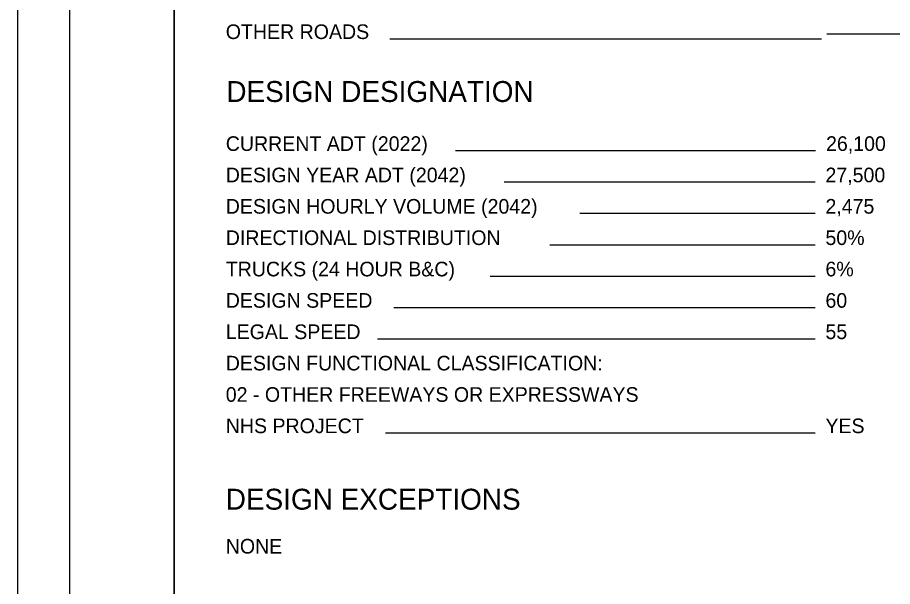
# Model space of a CAD drawing. Extents: x 0 to 34, y 0 to 22.
# Drawn here: x 0 to 8.38, y 5.64 to 11.08 of the extents above; entities that cross this region are included whole.
import ezdxf

# ---------------------------------------------------------------- set-up
doc = ezdxf.new("R2010")
doc.units = 0
for name, color, linetype in [('SH_Border', 7, 'Continuous'), ('SH_Cut_Line', 7, 'Continuous'), ('SH_Data', 7, 'Continuous'), ('SH_Text', 7, 'Continuous')]:
    doc.layers.add(name, color=color, linetype=linetype)

msp = doc.modelspace()

# ---------------------------------------------------------------- linework, layer by layer
at = {"layer": 'SH_Cut_Line'}
for p, q in [((9, 10.9223), (7.75, 10.9223)), ((7.7, 10.8767), (3.5657, 10.8767)), ((7.6424, 9.8062), (4.1936, 9.8062)), ((7.6368, 9.5062), (4.6592, 9.5062)), ((7.6368, 9.2062), (5.3852, 9.2062)), ((7.6368, 8.9062), (5.0988, 8.9062)), ((7.6368, 8.6062), (4.5259, 8.6062)), ((7.6368, 8.3062), (3.6035, 8.3062)), ((7.6368, 8.0062), (3.4488, 8.0062)), ((7.6368, 7.1062), (3.5243, 7.1062))]:
    msp.add_line(p, q, dxfattribs=at)
at = {"layer": 'SH_Data'}
for points in [[(0.5, 21.5), (1.5, 21.5), (1.5, 0.5), (0.5, 0.5)], [(1.5, 21.5), (33.5, 21.5), (33.5, 0.5), (1.5, 0.5)]]:
    msp.add_lwpolyline(points, close=True, dxfattribs=at)
at = {"layer": 'SH_Text'}
msp.add_lwpolyline([(0, 0), (34, 0), (34, 22), (0, 22)], close=True, dxfattribs=at)

# ---------------------------------------------------------------- texts
at = {"layer": 'SH_Border'}
for s, height, p in [('OTHER ROADS', 0.14, (1.9944, 10.8767)), ('CURRENT ADT (2022)', 0.14, (1.9944, 9.8062)), ('26,100', 0.14, (7.7424, 9.8062)), ('DESIGN YEAR ADT (2042)', 0.14, (1.9944, 9.5062)), ('27,500', 0.14, (7.7368, 9.5062)), ('DESIGN HOURLY VOLUME (2042)', 0.14, (1.9944, 9.2062)), ('2,475', 0.14, (7.7368, 9.2062)), ('DIRECTIONAL DISTRIBUTION', 0.14, (1.9944, 8.9062)), ('50%', 0.14, (7.7368, 8.9062)), ('TRUCKS (24 HOUR B&C)', 0.14, (1.9944, 8.6062)), ('6%', 0.14, (7.7368, 8.6062)), ('DESIGN SPEED', 0.14, (1.9944, 8.3062)), ('60', 0.14, (7.7368, 8.3062)), ('LEGAL SPEED', 0.14, (1.9944, 8.0062)), ('55', 0.14, (7.7368, 8.0062)), ('DESIGN FUNCTIONAL CLASSIFICATION:', 0.14, (1.9944, 7.7062)), ('02 - OTHER FREEWAYS OR EXPRESSWAYS', 0.14, (1.9944, 7.4062)), ('NHS PROJECT', 0.14, (1.9944, 7.1062)), ('YES', 0.14, (7.7368, 7.1062)), ('DESIGN EXCEPTIONS', 0.2, (1.9944, 6.3744)), ('NONE', 0.14, (1.9944, 5.9544))]:
    msp.add_text(s, height=height, dxfattribs=at).set_placement(p)
at = {"layer": 'SH_Cut_Line'}
msp.add_text('DESIGN DESIGNATION', height=0.2, dxfattribs=at).set_placement((2, 10.2747))

doc.saveas('drawing.dxf')
